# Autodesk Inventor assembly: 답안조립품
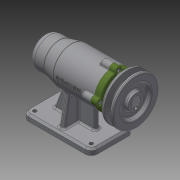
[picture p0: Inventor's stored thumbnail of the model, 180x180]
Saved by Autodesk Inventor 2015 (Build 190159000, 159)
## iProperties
Created: 2019-07
Part Number: 답안조립품
Document SubType Name: Assembly
Designer: now
Author: now
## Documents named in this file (12)
- C:\Users\now\Desktop\박은서\490704V1030\답안조립품.iam
- C:\Users\now\Desktop\박은서\490704V1030\V벨트풀리.ipt
- C:\Users\now\Desktop\박은서\490704V1030\멈춤나사 M3.ipt
- C:\Users\now\Desktop\박은서\490704V1030\베어링 6004.ipt
- C:\Users\now\Desktop\박은서\490704V1030\베어링 51202.ipt
- C:\Users\now\Desktop\박은서\490704V1030\본체.ipt
- C:\Users\now\Desktop\박은서\490704V1030\볼트 M4.ipt
- C:\Users\now\Desktop\박은서\490704V1030\어댑터슬리브.ipt
- C:\Users\now\Desktop\박은서\490704V1030\오일 실.ipt
- C:\Users\now\Desktop\박은서\490704V1030\축.ipt
- C:\Users\now\Desktop\박은서\490704V1030\커버.ipt
- C:\Users\now\Desktop\박은서\490704V1030\키 5 x 5 x 16.ipt
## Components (1 placed, 1 different names)
1. V벨트풀리:1
